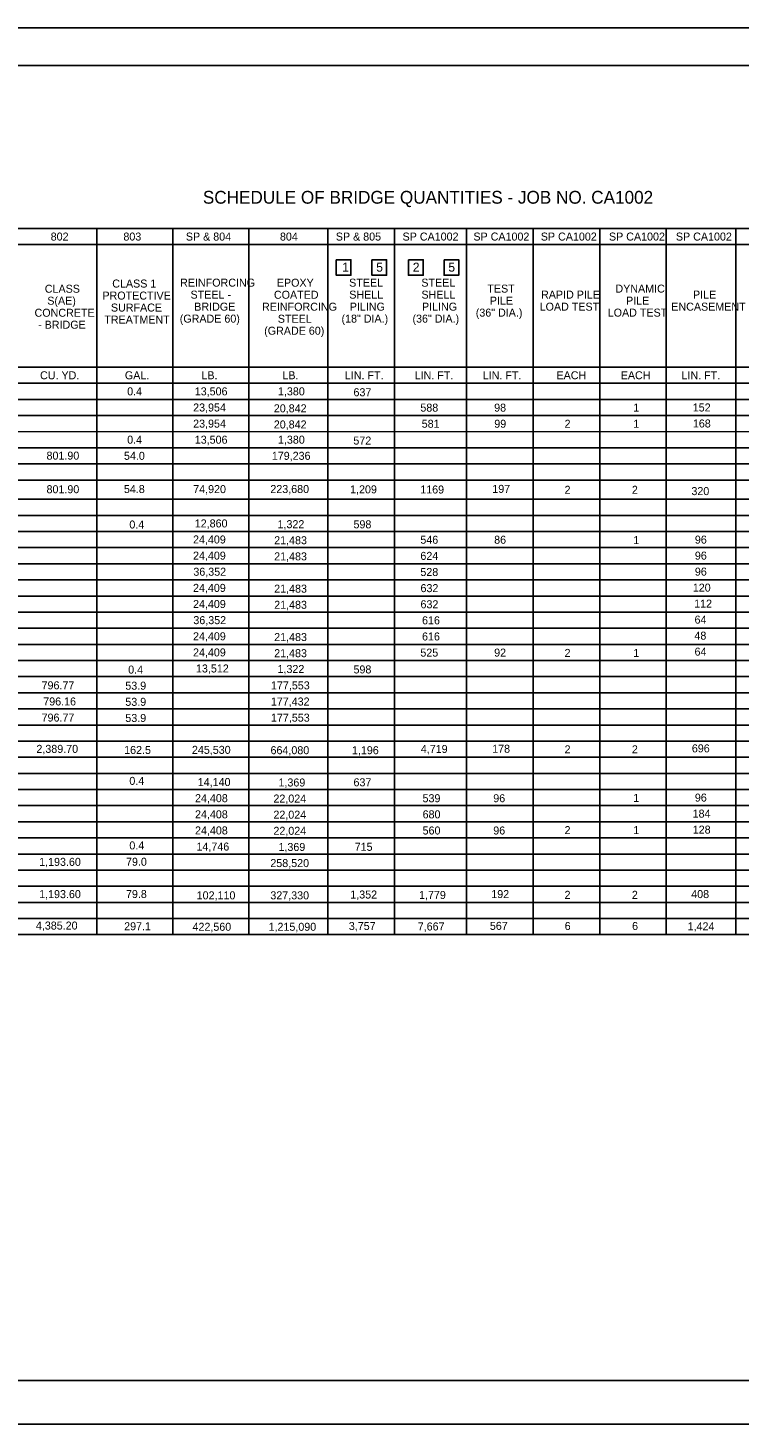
# Model space of a CAD drawing. Extents: x 117751.5 to 117785.6, y 28052.1 to 28074.
# Drawn here: x 117762.6 to 117773.71, y 28052.15 to 28073.96 of the extents above; entities that cross this region are included whole.
import ezdxf

# ---------------------------------------------------------------- set-up
doc = ezdxf.new("R2010")
doc.units = 0
for name, color, linetype in [('border', 7, 'Continuous'), ('Level 1', 7, 'Continuous'), ('Level 40', 7, 'Continuous'), ('Level 41', 7, 'Continuous'), ('Level 62', 7, 'Continuous')]:
    doc.layers.add(name, color=color, linetype=linetype)

msp = doc.modelspace()

# ---------------------------------------------------------------- linework, layer by layer
at = {"layer": 'border'}
for p, q in [((117753.15, 28073.371), (117785.161, 28073.371)), ((117785.161, 28052.826), (117753.15, 28052.826))]:
    msp.add_line(p, q, dxfattribs=at)
at = {"layer": 'Level 1'}
for p, q in [((117754.881, 28070.823), (117783.697, 28070.823)), ((117763.679, 28059.793), (117763.679, 28070.823)), ((117764.866, 28059.793), (117764.866, 28070.823)), ((117766.052, 28059.793), (117766.052, 28070.823)), ((117767.285, 28059.793), (117767.285, 28070.823)), ((117768.325, 28059.793), (117768.325, 28070.823)), ((117769.451, 28059.793), (117769.451, 28070.823)), ((117770.491, 28059.793), (117770.491, 28070.823)), ((117771.531, 28059.793), (117771.531, 28070.823)), ((117772.57, 28059.793), (117772.57, 28070.823)), ((117773.657, 28059.793), (117773.657, 28070.823)), ((117757.737, 28070.571), (117773.657, 28070.571)), ((117773.657, 28070.571), (117775.971, 28070.571)), ((117759.038, 28068.657), (117783.697, 28068.657)), ((117754.881, 28068.405), (117783.697, 28068.405)), ((117755.637, 28068.153), (117783.697, 28068.153)), ((117755.637, 28067.901), (117783.697, 28067.901)), ((117755.637, 28067.65), (117783.697, 28067.649)), ((117755.637, 28067.398), (117783.697, 28067.398)), ((117755.637, 28067.146), (117783.697, 28067.146)), ((117754.881, 28066.894), (117783.697, 28066.894)), ((117754.881, 28066.593), (117783.697, 28066.593)), ((117754.881, 28066.342), (117783.697, 28066.342)), ((117755.637, 28066.09), (117783.697, 28066.09)), ((117755.637, 28065.838), (117783.697, 28065.838)), ((117755.637, 28065.586), (117783.697, 28065.586)), ((117755.637, 28065.334), (117783.697, 28065.334)), ((117755.637, 28065.082), (117783.697, 28065.082)), ((117755.637, 28064.83), (117783.697, 28064.83)), ((117755.637, 28064.578), (117783.697, 28064.578)), ((117755.637, 28064.327), (117783.697, 28064.327)), ((117755.637, 28064.075), (117783.697, 28064.075)), ((117755.637, 28063.823), (117783.697, 28063.823)), ((117755.637, 28063.571), (117783.697, 28063.571)), ((117755.637, 28063.319), (117783.697, 28063.319)), ((117755.637, 28063.067), (117783.697, 28063.067)), ((117754.881, 28062.815), (117783.697, 28062.815)), ((117754.881, 28062.563), (117773.657, 28062.563)), ((117754.881, 28062.563), (117783.697, 28062.563)), ((117754.881, 28062.312), (117783.697, 28062.312)), ((117755.637, 28062.06), (117783.697, 28062.06)), ((117755.637, 28061.808), (117783.697, 28061.808)), ((117755.637, 28061.556), (117783.697, 28061.556)), ((117755.637, 28061.304), (117783.697, 28061.304)), ((117755.637, 28061.052), (117783.697, 28061.052)), ((117755.637, 28060.8), (117783.697, 28060.8)), ((117754.881, 28060.548), (117783.697, 28060.548)), ((117754.881, 28060.297), (117773.657, 28060.297)), ((117754.881, 28060.297), (117783.697, 28060.297)), ((117754.881, 28060.045), (117773.657, 28060.045)), ((117754.881, 28060.045), (117783.697, 28060.045)), ((117754.881, 28059.793), (117773.657, 28059.793)), ((117754.881, 28059.793), (117783.697, 28059.793))]:
    msp.add_line(p, q, dxfattribs=at)
at = {"layer": 'Level 40'}
for points in [[(117767.418, 28070.334), (117767.648, 28070.334), (117767.648, 28070.094), (117767.418, 28070.094)], [(117767.974, 28070.334), (117768.204, 28070.334), (117768.204, 28070.094), (117767.974, 28070.094)], [(117768.545, 28070.334), (117768.775, 28070.334), (117768.775, 28070.094), (117768.545, 28070.094)], [(117769.101, 28070.334), (117769.331, 28070.334), (117769.331, 28070.094), (117769.101, 28070.094)]]:
    msp.add_lwpolyline(points, close=True, dxfattribs=at)
at = {"layer": 'Level 62'}
msp.add_lwpolyline([(117751.53, 28073.957), (117785.648, 28073.957), (117785.648, 28052.147), (117751.53, 28052.147)], close=True, dxfattribs=at)

# ---------------------------------------------------------------- texts
at = {"layer": 'Level 40'}
for s, height, p in [('802', 0.125, (117762.96, 28070.635)), ('803', 0.125, (117764.095, 28070.635)), ('SP & 804', 0.125, (117765.07, 28070.635)), ('804', 0.125, (117766.539, 28070.635)), ('SP & 805', 0.125, (117767.411, 28070.635)), ('SP CA1002', 0.125, (117768.453, 28070.635)), ('SP CA1002', 0.125, (117769.559, 28070.635)), ('SP CA1002', 0.125, (117770.611, 28070.635)), ('SP CA1002', 0.125, (117771.675, 28070.635)), ('SP CA1002', 0.125, (117772.72, 28070.635)), ('1', 0.141, (117767.51, 28070.149)), ('5', 0.141, (117768.042, 28070.149)), ('2', 0.141, (117768.613, 28070.149)), ('5', 0.141, (117769.168, 28070.149)), ('CLASS', 0.125, (117762.868, 28069.82)), (' PROTECTIVE', 0.125, (117763.721, 28069.713)), ('CLASS 1', 0.125, (117763.921, 28069.901)), ('REINFORCING', 0.125, (117764.98, 28069.915)), ('STEEL -', 0.125, (117765.143, 28069.728)), ('COATED', 0.125, (117766.445, 28069.726)), ('EPOXY', 0.125, (117766.49, 28069.914)), ('STEEL', 0.125, (117767.619, 28069.915)), ('SHELL', 0.125, (117767.621, 28069.728)), ('STEEL', 0.125, (117768.746, 28069.915)), ('SHELL', 0.125, (117768.748, 28069.728)), ('TEST', 0.125, (117769.777, 28069.822)), ('RAPID PILE', 0.125, (117770.615, 28069.728)), ('DYNAMIC', 0.125, (117771.776, 28069.822)), ('PILE', 0.125, (117772.987, 28069.728)), ('S(AE)', 0.125, (117762.907, 28069.633)), ('SURFACE', 0.125, (117763.9, 28069.526)), ('BRIDGE', 0.125, (117765.201, 28069.54)), ('REINFORCING', 0.125, (117766.259, 28069.539)), ('PILING', 0.125, (117767.629, 28069.54)), ('PILING', 0.125, (117768.756, 28069.54)), ('PILE', 0.125, (117769.815, 28069.634)), ('LOAD TEST', 0.125, (117770.593, 28069.54)), ('PILE', 0.125, (117771.942, 28069.634)), ('ENCASEMENT', 0.125, (117772.648, 28069.54)), ('CONCRETE', 0.125, (117762.708, 28069.445)), ('TREATMENT', 0.125, (117763.797, 28069.338)), ('(GRADE 60) ', 0.125, (117764.975, 28069.353)), ('STEEL', 0.125, (117766.506, 28069.351)), ('(18" DIA.)', 0.125, (117767.5, 28069.353)), ('(36" DIA.)', 0.125, (117768.608, 28069.353)), ('(36" DIA.)', 0.125, (117769.596, 28069.447)), ('LOAD TEST', 0.125, (117771.656, 28069.447)), ('- BRIDGE', 0.125, (117762.764, 28069.258)), ('(GRADE 60)', 0.125, (117766.293, 28069.164)), ('CU. YD.', 0.125, (117762.794, 28068.468)), ('GAL.', 0.125, (117764.118, 28068.468)), ('LB.', 0.125, (117765.313, 28068.468)), ('LB.', 0.125, (117766.577, 28068.468)), ('LIN. FT.', 0.125, (117767.552, 28068.468)), ('LIN. FT.', 0.125, (117768.642, 28068.468)), ('LIN. FT.', 0.125, (117769.705, 28068.468)), ('EACH', 0.125, (117770.856, 28068.468)), ('EACH', 0.125, (117771.859, 28068.468)), ('LIN. FT.', 0.125, (117772.808, 28068.468)), ('0.4', 0.125, (117764.154, 28068.217)), ('13,506', 0.125, (117765.209, 28068.217)), ('1,380', 0.125, (117766.508, 28068.217)), ('637', 0.125, (117767.687, 28068.203)), ('23,954', 0.125, (117765.184, 28067.965)), ('588', 0.125, (117768.731, 28067.963)), ('98', 0.125, (117769.883, 28067.963)), ('1', 0.125, (117772.055, 28067.963)), ('152', 0.125, (117772.983, 28067.965)), ('20,842', 0.125, (117766.443, 28067.952)), ('23,954', 0.125, (117765.184, 28067.713)), ('20,842', 0.125, (117766.443, 28067.7)), ('581', 0.125, (117768.752, 28067.711)), ('99', 0.125, (117769.885, 28067.711)), ('2', 0.125, (117770.982, 28067.711)), ('1', 0.125, (117772.055, 28067.711)), ('168', 0.125, (117772.985, 28067.715)), ('0.4', 0.125, (117764.154, 28067.462)), ('13,506', 0.125, (117765.209, 28067.462)), ('1,380', 0.125, (117766.508, 28067.462)), ('572', 0.125, (117767.685, 28067.448)), ('801.90', 0.125, (117762.895, 28067.213)), ('54.0', 0.125, (117764.104, 28067.21)), ('179,236', 0.125, (117766.412, 28067.21)), ('801.90', 0.125, (117762.895, 28066.688)), ('54.8', 0.125, (117764.103, 28066.691)), ('74,920', 0.125, (117765.185, 28066.69)), ('223,680', 0.125, (117766.389, 28066.691)), ('1,209', 0.125, (117767.634, 28066.686)), ('1169', 0.125, (117768.729, 28066.684)), ('197', 0.125, (117769.854, 28066.694)), ('2', 0.125, (117770.982, 28066.679)), ('2', 0.125, (117772.033, 28066.679)), ('320', 0.125, (117772.962, 28066.659)), ('0.4', 0.125, (117764.188, 28066.137)), ('12,860', 0.125, (117765.209, 28066.154)), ('1,322', 0.125, (117766.501, 28066.142)), ('598', 0.125, (117767.687, 28066.14)), ('24,409', 0.125, (117765.182, 28065.903)), ('21,483', 0.125, (117766.449, 28065.891)), ('546', 0.125, (117768.731, 28065.899)), ('86', 0.125, (117769.883, 28065.899)), ('1', 0.125, (117772.055, 28065.893)), ('96', 0.125, (117773.016, 28065.901)), ('24,409', 0.125, (117765.182, 28065.651)), ('21,483', 0.125, (117766.449, 28065.639)), ('624', 0.125, (117768.731, 28065.647)), ('96', 0.125, (117773.016, 28065.651)), ('36,352', 0.125, (117765.187, 28065.399)), ('528', 0.125, (117768.731, 28065.395)), ('96', 0.125, (117773.016, 28065.401)), ('24,409', 0.125, (117765.182, 28065.147)), ('21,483', 0.125, (117766.449, 28065.135)), ('632', 0.125, (117768.733, 28065.143)), ('120', 0.125, (117772.984, 28065.151)), ('24,409', 0.125, (117765.182, 28064.895)), ('21,483', 0.125, (117766.449, 28064.883)), ('632', 0.125, (117768.733, 28064.891)), ('112', 0.125, (117773.005, 28064.901)), ('36,352', 0.125, (117765.187, 28064.643)), ('616', 0.125, (117768.757, 28064.64)), ('64', 0.125, (117773.011, 28064.651)), ('24,409', 0.125, (117765.182, 28064.391)), ('21,483', 0.125, (117766.449, 28064.379)), ('616', 0.125, (117768.757, 28064.388)), ('48', 0.125, (117773.009, 28064.401)), ('24,409', 0.125, (117765.182, 28064.139)), ('21,483', 0.125, (117766.449, 28064.127)), ('525', 0.125, (117768.731, 28064.136)), ('92', 0.125, (117769.883, 28064.136)), ('2', 0.125, (117770.982, 28064.131)), ('1', 0.125, (117772.055, 28064.131)), ('64', 0.125, (117773.011, 28064.151)), ('0.4', 0.125, (117764.17, 28063.871)), ('13,512', 0.125, (117765.228, 28063.888)), ('1,322', 0.125, (117766.501, 28063.88)), ('598', 0.125, (117767.687, 28063.873)), ('796.77', 0.125, (117762.818, 28063.625)), ('53.9', 0.125, (117764.125, 28063.619)), ('177,553', 0.125, (117766.399, 28063.624)), ('796.16', 0.125, (117762.844, 28063.373)), ('53.9', 0.125, (117764.125, 28063.367)), ('177,432', 0.125, (117766.397, 28063.372)), ('796.77', 0.125, (117762.818, 28063.121)), ('53.9', 0.125, (117764.125, 28063.115)), ('177,553', 0.125, (117766.399, 28063.12)), ('2,389.70', 0.125, (117762.737, 28062.632)), ('162.5', 0.125, (117764.107, 28062.615)), ('245,530', 0.125, (117765.165, 28062.617)), ('664,080', 0.125, (117766.392, 28062.611)), ('1,196', 0.125, (117767.663, 28062.611)), ('4,719', 0.125, (117768.738, 28062.631)), ('178', 0.125, (117769.852, 28062.634)), ('2', 0.125, (117770.982, 28062.625)), ('2', 0.125, (117772.033, 28062.625)), ('696', 0.125, (117772.969, 28062.64)), ('0.4', 0.125, (117764.188, 28062.132)), ('14,140', 0.125, (117765.256, 28062.114)), ('1,369', 0.125, (117766.516, 28062.107)), ('637', 0.125, (117767.687, 28062.11)), ('24,408', 0.125, (117765.213, 28061.862)), ('22,024', 0.125, (117766.437, 28061.856)), ('539', 0.125, (117768.765, 28061.861)), ('96', 0.125, (117769.869, 28061.861)), ('1', 0.125, (117772.055, 28061.867)), ('96', 0.125, (117773.016, 28061.871)), ('24,408', 0.125, (117765.213, 28061.61)), ('22,024', 0.125, (117766.437, 28061.604)), ('680', 0.125, (117768.766, 28061.609)), ('184', 0.125, (117772.981, 28061.621)), ('24,408', 0.125, (117765.213, 28061.358)), ('22,024', 0.125, (117766.437, 28061.352)), ('560', 0.125, (117768.766, 28061.357)), ('96', 0.125, (117769.869, 28061.357)), ('2', 0.125, (117770.982, 28061.363)), ('1', 0.125, (117772.055, 28061.363)), ('128', 0.125, (117772.983, 28061.371)), ('0.4', 0.125, (117764.188, 28061.124)), ('14,746', 0.125, (117765.236, 28061.106)), ('1,369', 0.125, (117766.516, 28061.1)), ('715', 0.125, (117767.706, 28061.102)), ('1,193.60', 0.125, (117762.78, 28060.867)), ('79.0', 0.125, (117764.136, 28060.869)), ('258,520', 0.125, (117766.389, 28060.848)), ('1,193.60', 0.125, (117762.78, 28060.363)), ('79.8', 0.125, (117764.135, 28060.365)), ('102,110', 0.125, (117765.239, 28060.344)), ('327,330', 0.125, (117766.389, 28060.344)), ('1,352', 0.125, (117767.637, 28060.357)), ('1,779', 0.125, (117768.71, 28060.35)), ('192', 0.125, (117769.838, 28060.364)), ('2', 0.125, (117770.982, 28060.352)), ('2', 0.125, (117772.033, 28060.352)), ('408', 0.125, (117772.959, 28060.364)), ('4,385.20', 0.125, (117762.729, 28059.872)), ('297.1', 0.125, (117764.107, 28059.861)), ('422,560', 0.125, (117765.174, 28059.853)), ('1,215,090', 0.125, (117766.361, 28059.853)), ('3,757', 0.125, (117767.614, 28059.865)), ('7,667', 0.125, (117768.69, 28059.858)), ('567', 0.125, (117769.816, 28059.867)), ('6', 0.125, (117770.984, 28059.865)), ('6', 0.125, (117772.036, 28059.865)), ('1,424', 0.125, (117772.903, 28059.86))]:
    msp.add_text(s, height=height, dxfattribs=at).set_placement(p)
at = {"layer": 'Level 41'}
msp.add_text(' SCHEDULE OF BRIDGE QUANTITIES - JOB NO. CA1002 ', height=0.2, dxfattribs=at).set_placement((117765.261, 28071.211))

doc.saveas('drawing.dxf')
